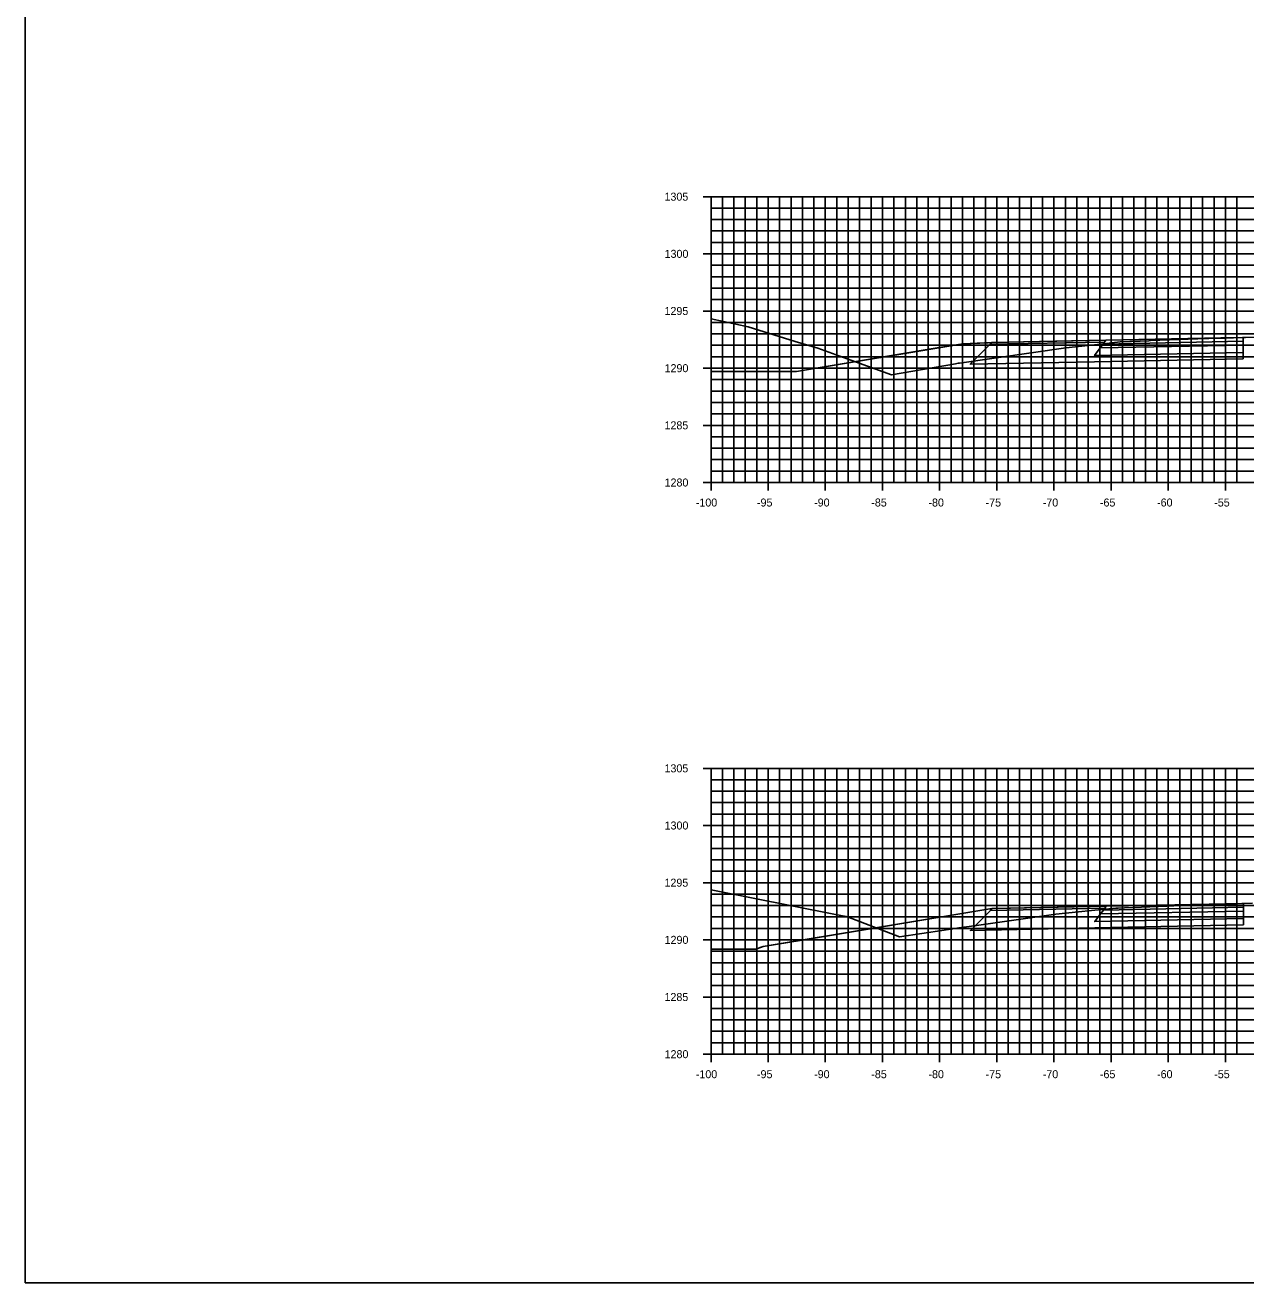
# Model space of a CAD drawing. Extents: x 674939 to 678919, y 750652 to 765176.
# Drawn here: x 677778.5 to 677885.3, y 758052.6 to 758162.6 of the extents above; entities that cross this region are included whole.
import ezdxf

# ---------------------------------------------------------------- set-up
doc = ezdxf.new("R2010")
doc.units = 0
for name, color, linetype in [('R_Alt Surface', 7, 'Continuous'), ('R_Axis', 7, 'Continuous'), ('R_Axis Annot', 7, 'Continuous'), ('R_Exist Surface', 7, 'Continuous'), ('R_Fin Surface', 7, 'Continuous'), ('R_Grid', 7, 'Continuous'), ('R_No Plot', 7, 'Continuous')]:
    doc.layers.add(name, color=color, linetype=linetype)

msp = doc.modelspace()

# ---------------------------------------------------------------- linework, layer by layer
for points in [[(677860.57, 758134.69), (677846, 758132.26)], [(677863.1, 758085.29), (677843.1, 758081.96), (677842.43, 758081.73)]]:
    msp.add_lwpolyline(points)
at = {"layer": 'R_Alt Surface'}
for points in [[(677885.08, 758133.91), (677885.08, 758133.37), (677872.08, 758133.11), (677861.2, 758132.89), (677862.96, 758134.64)], [(677885.1, 758084.41), (677885.1, 758083.87), (677872.1, 758083.61), (677861.22, 758083.38), (677862.98, 758085.13)]]:
    msp.add_lwpolyline(points, dxfattribs=at)
for points in [[(677885.08, 758134.57), (677885.08, 758133.91), (677872.08, 758133.65), (677872.58, 758134.32)], [(677885.08, 758134.9), (677885.08, 758134.57), (677872.58, 758134.32), (677872.83, 758134.65)], [(677885.1, 758085.07), (677885.1, 758084.41), (677872.1, 758084.15), (677872.6, 758084.82)], [(677885.1, 758085.4), (677885.1, 758085.07), (677872.6, 758084.82), (677872.85, 758085.15)]]:
    msp.add_lwpolyline(points, close=True, dxfattribs=at)
at = {"layer": 'R_Axis'}
for p, q in [((677837.83, 758147.55), (677839.23, 758147.55)), ((677838.53, 758122.55), (677838.53, 758147.55)), ((677838.53, 758146.55), (677838.88, 758146.55)), ((677838.53, 758145.55), (677838.88, 758145.55)), ((677838.53, 758144.55), (677838.88, 758144.55)), ((677838.53, 758143.55), (677838.88, 758143.55)), ((677837.83, 758142.55), (677839.23, 758142.55)), ((677838.53, 758141.55), (677838.88, 758141.55)), ((677838.53, 758140.55), (677838.88, 758140.55)), ((677838.53, 758139.55), (677838.88, 758139.55)), ((677838.53, 758138.55), (677838.88, 758138.55)), ((677837.83, 758137.55), (677839.23, 758137.55)), ((677838.53, 758136.55), (677838.88, 758136.55)), ((677838.53, 758135.55), (677838.88, 758135.55)), ((677838.53, 758134.55), (677838.88, 758134.55)), ((677838.53, 758133.55), (677838.88, 758133.55)), ((677837.83, 758132.55), (677839.23, 758132.55)), ((677838.53, 758131.55), (677838.88, 758131.55)), ((677838.53, 758130.55), (677838.88, 758130.55)), ((677838.53, 758129.55), (677838.88, 758129.55)), ((677838.53, 758128.55), (677838.88, 758128.55)), ((677837.83, 758127.55), (677839.23, 758127.55)), ((677838.53, 758126.55), (677838.88, 758126.55)), ((677838.53, 758125.55), (677838.88, 758125.55)), ((677838.53, 758124.55), (677838.88, 758124.55)), ((677838.53, 758123.55), (677838.88, 758123.55)), ((677837.83, 758122.55), (677839.23, 758122.55)), ((677838.53, 758121.85), (677838.53, 758123.25)), ((677838.53, 758122.55), (678038.53, 758122.55)), ((677843.53, 758121.85), (677843.53, 758123.25)), ((677848.53, 758121.85), (677848.53, 758123.25)), ((677853.53, 758121.85), (677853.53, 758123.25)), ((677858.53, 758121.85), (677858.53, 758123.25)), ((677863.53, 758121.85), (677863.53, 758123.25)), ((677868.53, 758121.85), (677868.53, 758123.25)), ((677873.53, 758121.85), (677873.53, 758123.25)), ((677878.53, 758121.85), (677878.53, 758123.25)), ((677883.53, 758121.85), (677883.53, 758123.25)), ((677837.83, 758097.55), (677839.23, 758097.55)), ((677838.53, 758072.55), (677838.53, 758097.55)), ((677838.53, 758096.55), (677838.88, 758096.55)), ((677838.53, 758095.55), (677838.88, 758095.55)), ((677838.53, 758094.55), (677838.88, 758094.55)), ((677837.83, 758092.55), (677839.23, 758092.55)), ((677838.53, 758093.55), (677838.88, 758093.55)), ((677838.53, 758091.55), (677838.88, 758091.55)), ((677838.53, 758090.55), (677838.88, 758090.55)), ((677838.53, 758089.55), (677838.88, 758089.55)), ((677838.53, 758088.55), (677838.88, 758088.55)), ((677837.83, 758087.55), (677839.23, 758087.55)), ((677838.53, 758086.55), (677838.88, 758086.55)), ((677838.53, 758085.55), (677838.88, 758085.55)), ((677838.53, 758084.55), (677838.88, 758084.55)), ((677838.53, 758083.55), (677838.88, 758083.55)), ((677837.83, 758082.55), (677839.23, 758082.55)), ((677838.53, 758081.55), (677838.88, 758081.55)), ((677838.53, 758080.55), (677838.88, 758080.55)), ((677838.53, 758079.55), (677838.88, 758079.55)), ((677838.53, 758078.55), (677838.88, 758078.55)), ((677837.83, 758077.55), (677839.23, 758077.55)), ((677838.53, 758076.55), (677838.88, 758076.55)), ((677838.53, 758075.55), (677838.88, 758075.55)), ((677838.53, 758074.55), (677838.88, 758074.55)), ((677838.53, 758073.55), (677838.88, 758073.55)), ((677838.53, 758071.85), (677838.53, 758073.25)), ((677843.53, 758071.85), (677843.53, 758073.25)), ((677848.53, 758071.85), (677848.53, 758073.25)), ((677853.53, 758071.85), (677853.53, 758073.25)), ((677858.53, 758071.85), (677858.53, 758073.25)), ((677863.53, 758071.85), (677863.53, 758073.25)), ((677868.53, 758071.85), (677868.53, 758073.25)), ((677873.53, 758071.85), (677873.53, 758073.25)), ((677878.53, 758071.85), (677878.53, 758073.25)), ((677883.53, 758071.85), (677883.53, 758073.25)), ((677837.83, 758072.55), (677839.23, 758072.55)), ((677838.53, 758072.55), (678038.53, 758072.55))]:
    msp.add_line(p, q, dxfattribs=at)
at = {"layer": 'R_Exist Surface'}
for points in [[(677838.53, 758136.86), (677841.79, 758136.18), (677845.89, 758134.89), (677847.88, 758134.31), (677849.81, 758133.61), (677853.6, 758132.23), (677854.31, 758131.97), (677859.93, 758132.94), (677860.16, 758132.98), (677860.26, 758133), (677869.58, 758134.34), (677872.62, 758134.65), (677874.31, 758134.86), (677875.18, 758134.89), (677875.31, 758134.89), (677876.84, 758134.95), (677876.97, 758134.96), (677881.94, 758135.14), (677882.09, 758135.15), (677883.43, 758135.17), (677883.48, 758135.17), (677885.01, 758135.23), (677885.03, 758135.23), (677885.08, 758135.23), (677885.09, 758135.23), (677885.28, 758135.24), (677891.35, 758135.44)], [(677838.53, 758086.91), (677849.26, 758084.81), (677850.36, 758084.6), (677850.52, 758084.54), (677850.84, 758084.43), (677855.03, 758082.81), (677858.94, 758083.41), (677859.69, 758083.52), (677860.21, 758083.59), (677861.56, 758083.78), (677868.69, 758084.8), (677870.69, 758085.01), (677871.81, 758085.12), (677873.95, 758085.31), (677873.99, 758085.31), (677874.14, 758085.32), (677874.71, 758085.36), (677878.41, 758085.51), (677880.26, 758085.58), (677881.54, 758085.62), (677882.23, 758085.63), (677883.23, 758085.67), (677884.08, 758085.69), (677884.48, 758085.69), (677884.96, 758085.72), (677885.08, 758085.73), (677885.1, 758085.73), (677885.9, 758085.77)]]:
    msp.add_lwpolyline(points, dxfattribs=at)
at = {"layer": 'R_Fin Surface'}
for points in [[(677863.08, 758134.79), (677860.57, 758134.69)], [(677863.08, 758134.79), (677873.08, 758134.99), (677885.08, 758135.23)], [(677863.1, 758085.29), (677873.1, 758085.49), (677885.1, 758085.73)], [(677863.1, 758085.29), (677863.1, 758085.29)]]:
    msp.add_lwpolyline(points, dxfattribs=at)
for points in [[(677873.08, 758134.99), (677863.08, 758134.79), (677862.96, 758134.64), (677872.96, 758134.83)], [(677885.08, 758135.23), (677885.08, 758134.9), (677872.83, 758134.65), (677873.08, 758134.99)], [(677873.1, 758085.49), (677863.1, 758085.29), (677862.98, 758085.13), (677872.98, 758085.33)], [(677885.1, 758085.73), (677885.1, 758085.4), (677872.85, 758085.15), (677873.1, 758085.49)]]:
    msp.add_lwpolyline(points, close=True, dxfattribs=at)
at = {"layer": 'R_Grid'}
for p, q in [((677838.53, 758147.55), (678038.53, 758147.55)), ((677838.53, 758122.55), (677838.53, 758147.55)), ((677839.53, 758122.55), (677839.53, 758147.55)), ((677840.53, 758122.55), (677840.53, 758147.55)), ((677841.53, 758122.55), (677841.53, 758147.55)), ((677842.53, 758122.55), (677842.53, 758147.55)), ((677843.53, 758122.55), (677843.53, 758147.55)), ((677844.53, 758122.55), (677844.53, 758147.55)), ((677845.53, 758122.55), (677845.53, 758147.55)), ((677846.53, 758122.55), (677846.53, 758147.55)), ((677847.53, 758122.55), (677847.53, 758147.55)), ((677848.53, 758122.55), (677848.53, 758147.55)), ((677849.53, 758122.55), (677849.53, 758147.55)), ((677850.53, 758122.55), (677850.53, 758147.55)), ((677851.53, 758122.55), (677851.53, 758147.55)), ((677852.53, 758122.55), (677852.53, 758147.55)), ((677853.53, 758122.55), (677853.53, 758147.55)), ((677854.53, 758122.55), (677854.53, 758147.55)), ((677855.53, 758122.55), (677855.53, 758147.55)), ((677856.53, 758122.55), (677856.53, 758147.55)), ((677857.53, 758122.55), (677857.53, 758147.55)), ((677858.53, 758122.55), (677858.53, 758147.55)), ((677859.53, 758122.55), (677859.53, 758147.55)), ((677860.53, 758122.55), (677860.53, 758147.55)), ((677861.53, 758122.55), (677861.53, 758147.55)), ((677862.53, 758122.55), (677862.53, 758147.55)), ((677863.53, 758122.55), (677863.53, 758147.55)), ((677864.53, 758122.55), (677864.53, 758147.55)), ((677865.53, 758122.55), (677865.53, 758147.55)), ((677866.53, 758122.55), (677866.53, 758147.55)), ((677867.53, 758122.55), (677867.53, 758147.55)), ((677868.53, 758122.55), (677868.53, 758147.55)), ((677869.53, 758122.55), (677869.53, 758147.55)), ((677870.53, 758122.55), (677870.53, 758147.55)), ((677871.53, 758122.55), (677871.53, 758147.55)), ((677872.53, 758122.55), (677872.53, 758147.55)), ((677873.53, 758122.55), (677873.53, 758147.55)), ((677874.53, 758122.55), (677874.53, 758147.55)), ((677875.53, 758122.55), (677875.53, 758147.55)), ((677876.53, 758122.55), (677876.53, 758147.55)), ((677877.53, 758122.55), (677877.53, 758147.55)), ((677878.53, 758122.55), (677878.53, 758147.55)), ((677879.53, 758122.55), (677879.53, 758147.55)), ((677880.53, 758122.55), (677880.53, 758147.55)), ((677881.53, 758122.55), (677881.53, 758147.55)), ((677882.53, 758122.55), (677882.53, 758147.55)), ((677883.53, 758122.55), (677883.53, 758147.55)), ((677884.53, 758122.55), (677884.53, 758147.55)), ((677838.53, 758146.55), (678038.53, 758146.55)), ((677838.53, 758145.55), (678038.53, 758145.55)), ((677838.53, 758144.55), (678038.53, 758144.55)), ((677838.53, 758143.55), (678038.53, 758143.55)), ((677838.53, 758142.55), (678038.53, 758142.55)), ((677838.53, 758141.55), (678038.53, 758141.55)), ((677838.53, 758140.55), (678038.53, 758140.55)), ((677838.53, 758139.55), (678038.53, 758139.55)), ((677838.53, 758138.55), (678038.53, 758138.55)), ((677838.53, 758137.55), (678038.53, 758137.55)), ((677838.53, 758136.55), (678038.53, 758136.55)), ((677838.53, 758135.55), (678038.53, 758135.55)), ((677838.53, 758134.55), (678038.53, 758134.55)), ((677838.53, 758133.55), (678038.53, 758133.55)), ((677838.53, 758132.55), (678038.53, 758132.55)), ((677838.53, 758131.55), (678038.53, 758131.55)), ((677838.53, 758130.55), (678038.53, 758130.55)), ((677838.53, 758129.55), (678038.53, 758129.55)), ((677838.53, 758128.55), (678038.53, 758128.55)), ((677838.53, 758127.55), (678038.53, 758127.55)), ((677838.53, 758126.55), (678038.53, 758126.55)), ((677838.53, 758125.55), (678038.53, 758125.55)), ((677838.53, 758124.55), (678038.53, 758124.55)), ((677838.53, 758123.55), (678038.53, 758123.55)), ((677838.53, 758122.55), (678038.53, 758122.55)), ((677838.53, 758097.55), (678038.53, 758097.55)), ((677838.53, 758072.55), (677838.53, 758097.55)), ((677839.53, 758072.55), (677839.53, 758097.55)), ((677840.53, 758072.55), (677840.53, 758097.55)), ((677841.53, 758072.55), (677841.53, 758097.55)), ((677842.53, 758072.55), (677842.53, 758097.55)), ((677843.53, 758072.55), (677843.53, 758097.55)), ((677844.53, 758072.55), (677844.53, 758097.55)), ((677845.53, 758072.55), (677845.53, 758097.55)), ((677846.53, 758072.55), (677846.53, 758097.55)), ((677847.53, 758072.55), (677847.53, 758097.55)), ((677848.53, 758072.55), (677848.53, 758097.55)), ((677849.53, 758072.55), (677849.53, 758097.55)), ((677850.53, 758072.55), (677850.53, 758097.55)), ((677851.53, 758072.55), (677851.53, 758097.55)), ((677852.53, 758072.55), (677852.53, 758097.55)), ((677853.53, 758072.55), (677853.53, 758097.55)), ((677854.53, 758072.55), (677854.53, 758097.55)), ((677855.53, 758072.55), (677855.53, 758097.55)), ((677856.53, 758072.55), (677856.53, 758097.55)), ((677857.53, 758072.55), (677857.53, 758097.55)), ((677858.53, 758072.55), (677858.53, 758097.55)), ((677859.53, 758072.55), (677859.53, 758097.55)), ((677860.53, 758072.55), (677860.53, 758097.55)), ((677861.53, 758072.55), (677861.53, 758097.55)), ((677862.53, 758072.55), (677862.53, 758097.55)), ((677863.53, 758072.55), (677863.53, 758097.55)), ((677864.53, 758072.55), (677864.53, 758097.55)), ((677865.53, 758072.55), (677865.53, 758097.55)), ((677866.53, 758072.55), (677866.53, 758097.55)), ((677867.53, 758072.55), (677867.53, 758097.55)), ((677868.53, 758072.55), (677868.53, 758097.55)), ((677869.53, 758072.55), (677869.53, 758097.55)), ((677870.53, 758072.55), (677870.53, 758097.55)), ((677871.53, 758072.55), (677871.53, 758097.55)), ((677872.53, 758072.55), (677872.53, 758097.55)), ((677873.53, 758072.55), (677873.53, 758097.55)), ((677874.53, 758072.55), (677874.53, 758097.55)), ((677875.53, 758072.55), (677875.53, 758097.55)), ((677876.53, 758072.55), (677876.53, 758097.55)), ((677877.53, 758072.55), (677877.53, 758097.55)), ((677878.53, 758072.55), (677878.53, 758097.55)), ((677879.53, 758072.55), (677879.53, 758097.55)), ((677880.53, 758072.55), (677880.53, 758097.55)), ((677881.53, 758072.55), (677881.53, 758097.55)), ((677882.53, 758072.55), (677882.53, 758097.55)), ((677883.53, 758072.55), (677883.53, 758097.55)), ((677884.53, 758072.55), (677884.53, 758097.55)), ((677838.53, 758096.55), (678038.53, 758096.55)), ((677838.53, 758095.55), (678038.53, 758095.55)), ((677838.53, 758094.55), (678038.53, 758094.55)), ((677838.53, 758093.55), (678038.53, 758093.55)), ((677838.53, 758092.55), (678038.53, 758092.55)), ((677838.53, 758091.55), (678038.53, 758091.55)), ((677838.53, 758090.55), (678038.53, 758090.55)), ((677838.53, 758089.55), (678038.53, 758089.55)), ((677838.53, 758088.55), (678038.53, 758088.55)), ((677838.53, 758087.55), (678038.53, 758087.55)), ((677838.53, 758086.55), (678038.53, 758086.55)), ((677838.53, 758085.55), (678038.53, 758085.55)), ((677838.53, 758084.55), (678038.53, 758084.55)), ((677838.53, 758083.55), (678038.53, 758083.55)), ((677838.53, 758082.55), (678038.53, 758082.55)), ((677838.53, 758081.55), (678038.53, 758081.55)), ((677838.53, 758080.55), (678038.53, 758080.55)), ((677838.53, 758079.55), (678038.53, 758079.55)), ((677838.53, 758078.55), (678038.53, 758078.55)), ((677838.53, 758077.55), (678038.53, 758077.55)), ((677838.53, 758076.55), (678038.53, 758076.55)), ((677838.53, 758075.55), (678038.53, 758075.55)), ((677838.53, 758074.55), (678038.53, 758074.55)), ((677838.53, 758073.55), (678038.53, 758073.55)), ((677838.53, 758072.55), (678038.53, 758072.55))]:
    msp.add_line(p, q, dxfattribs=at)
at = {"layer": 'R_No Plot'}
msp.add_lwpolyline([(677778.53, 758052.55), (678118.53, 758052.55), (678118.53, 758272.55), (677778.53, 758272.55)], close=True, dxfattribs=at)
for points in [[(677838.53, 758132.26), (677844.71, 758132.26), (677846, 758132.26), (677858.14, 758134.29), (677860.57, 758134.69), (677862.78, 758134.78), (677863.08, 758134.79), (677871.45, 758134.96), (677873.08, 758134.99), (677883.12, 758135.19), (677885.08, 758135.23)], [(677838.53, 758081.73), (677842.43, 758081.73), (677842.55, 758081.77), (677843.1, 758081.96), (677846.33, 758082.5), (677863.1, 758085.29), (677864.72, 758085.32), (677873.1, 758085.49), (677875.05, 758085.53), (677885.1, 758085.73)]]:
    msp.add_lwpolyline(points, dxfattribs=at)

# ---------------------------------------------------------------- texts
at = {"layer": 'R_Axis Annot'}
for s, p in [('1305', (677834.46, 758147.2)), ('1300', (677834.47, 758142.2)), ('1295', (677834.46, 758137.2)), ('1290', (677834.47, 758132.2)), ('1285', (677834.46, 758127.2)), ('1280', (677834.47, 758122.2)), ('-100', (677837.2, 758120.45)), ('-95', (677842.55, 758120.45)), ('-90', (677847.55, 758120.45)), ('-85', (677852.55, 758120.45)), ('-80', (677857.55, 758120.45)), ('-75', (677862.55, 758120.45)), ('-70', (677867.55, 758120.45)), ('-65', (677872.55, 758120.45)), ('-60', (677877.55, 758120.45)), ('-55', (677882.55, 758120.45)), ('1305', (677834.46, 758097.2)), ('1300', (677834.47, 758092.2)), ('1295', (677834.46, 758087.2)), ('1290', (677834.47, 758082.2)), ('1285', (677834.46, 758077.2)), ('1280', (677834.47, 758072.2)), ('-100', (677837.2, 758070.45)), ('-95', (677842.55, 758070.45)), ('-90', (677847.55, 758070.45)), ('-85', (677852.55, 758070.45)), ('-80', (677857.55, 758070.45)), ('-75', (677862.55, 758070.45)), ('-70', (677867.55, 758070.45)), ('-65', (677872.55, 758070.45)), ('-60', (677877.55, 758070.45)), ('-55', (677882.55, 758070.45))]:
    msp.add_text(s, height=0.7, dxfattribs=at).set_placement(p)

doc.saveas('drawing.dxf')
